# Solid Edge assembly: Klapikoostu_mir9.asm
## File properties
Author: Türk
Template: Iso Assembly.asm
Last saved by: Türk
Revision: 3
Application: Solid Edge
Username: Türk
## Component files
Klapipuks.par
Klapp.par
Klapi vedru_mir2.par
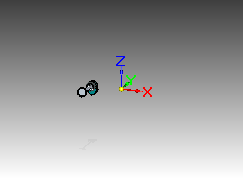
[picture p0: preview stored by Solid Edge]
